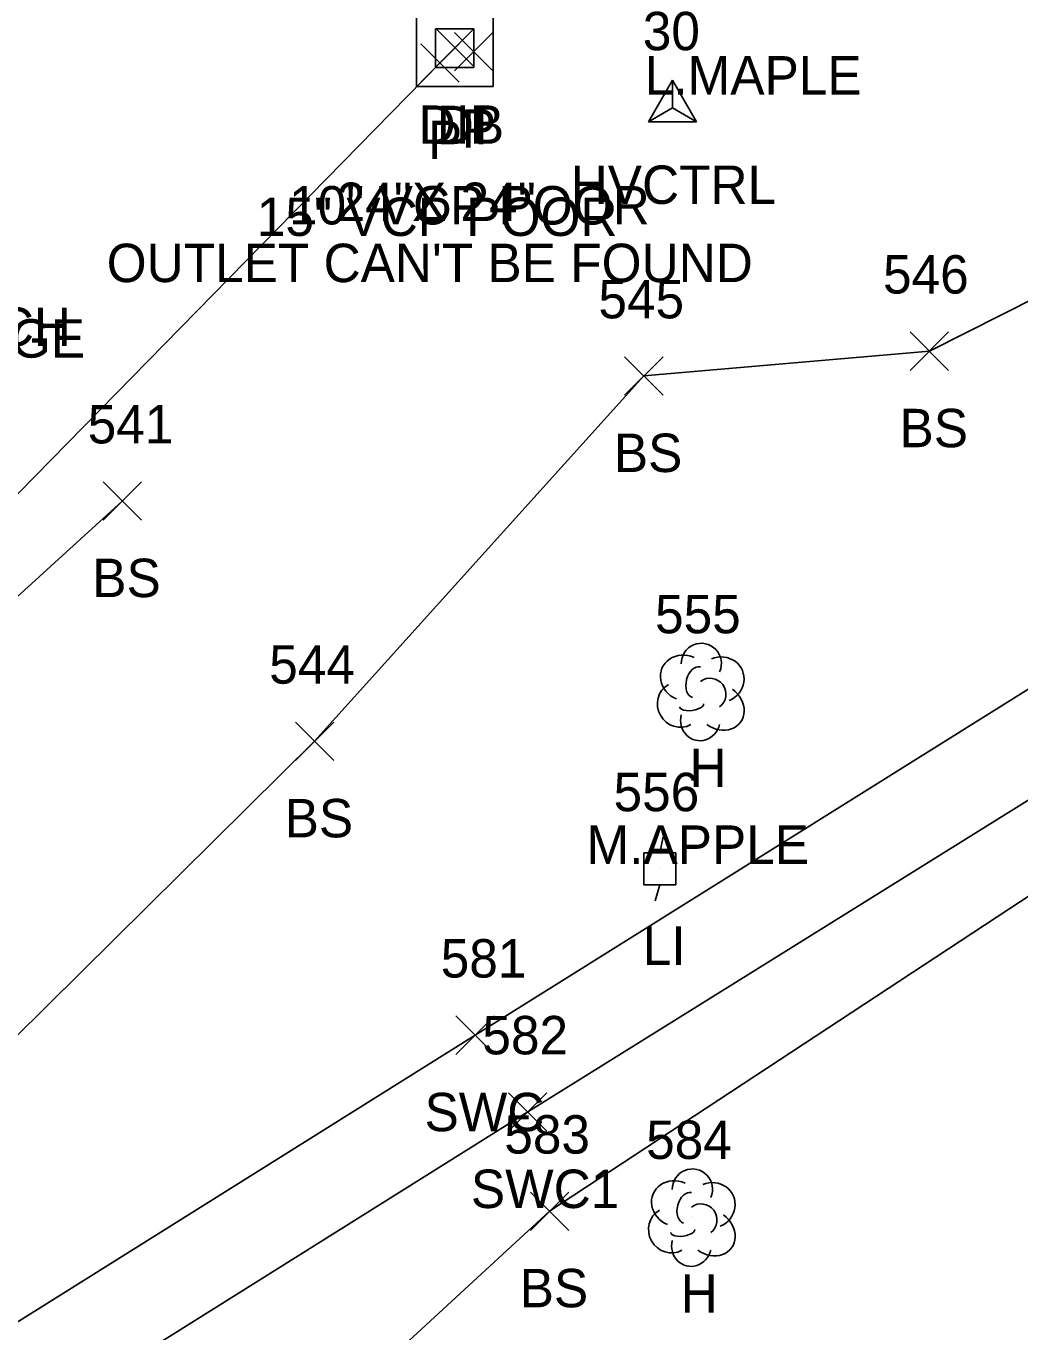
# Model space of a CAD drawing. Extents: x 1462668 to 1465147, y 550359 to 557351.
# Drawn here: x 1464825.9 to 1464877.7, y 552486.8 to 552554.8 of the extents above; entities that cross this region are included whole.
import ezdxf

# ---------------------------------------------------------------- set-up
doc = ezdxf.new("R2010")
doc.units = 0
for name, color, linetype in [('C_A', 7, 'Continuous'), ('C_I', 7, 'Continuous'), ('CPSM', 7, 'Continuous'), ('D_A', 7, 'Continuous'), ('D_C', 7, 'Continuous'), ('D_TIC', 7, 'Continuous'), ('DCP', 7, 'Continuous'), ('DS', 7, 'Continuous'), ('L_A', 7, 'Continuous'), ('L_C', 7, 'Continuous'), ('L_I', 7, 'Continuous'), ('L_TIC', 7, 'Continuous'), ('LELB', 7, 'Continuous'), ('LTD', 7, 'Continuous'), ('R_A', 7, 'Continuous'), ('R_I', 7, 'Continuous'), ('R_TIC', 7, 'Continuous'), ('RSW', 7, 'Continuous'), ('U_A', 7, 'Continuous'), ('U_I', 7, 'Continuous'), ('ULP', 7, 'Continuous')]:
    doc.layers.add(name, color=color, linetype=linetype)

msp = doc.modelspace()

# ---------------------------------------------------------------- linework, layer by layer
at = {"layer": 'CPSM'}
for p, q in [((1464858.341, 552549.777), (1464859.591, 552551.942)), ((1464860.841, 552549.777), (1464859.591, 552551.942)), ((1464859.591, 552550.499), (1464859.591, 552551.942)), ((1464858.341, 552549.777), (1464859.591, 552550.499)), ((1464859.591, 552550.499), (1464859.591, 552550.499)), ((1464859.591, 552550.499), (1464860.841, 552549.777)), ((1464858.341, 552549.777), (1464860.841, 552549.777))]:
    msp.add_line(p, q, dxfattribs=at)
at = {"layer": 'D_TIC'}
for points in [[(1464847.258, 552552.629), (1464849.258, 552554.629)], [(1464849.258, 552552.629), (1464847.258, 552554.629)], [(1464848.234, 552552.429), (1464850.234, 552554.429)], [(1464850.234, 552552.429), (1464848.234, 552554.429)], [(1464846.475, 552551.831), (1464848.475, 552553.831)], [(1464848.475, 552551.831), (1464846.475, 552553.831)]]:
    msp.add_lwpolyline(points, dxfattribs=at)
at = {"layer": 'DCP'}
msp.add_lwpolyline([(1464802.754, 552507.235), (1464847.475, 552552.831)], dxfattribs=at)
at = {"layer": 'DS'}
for p, q in [((1464846.25, 552551.608), (1464846.25, 552555.608)), ((1464850.25, 552555.608), (1464850.25, 552551.608)), ((1464847.25, 552552.608), (1464847.25, 552554.608)), ((1464847.25, 552554.608), (1464849.25, 552554.608)), ((1464849.25, 552554.608), (1464849.25, 552552.608)), ((1464848.256, 552553.609), (1464848.256, 552553.609)), ((1464848.256, 552553.609), (1464848.256, 552553.609)), ((1464849.25, 552552.608), (1464847.25, 552552.608)), ((1464850.25, 552551.608), (1464846.25, 552551.608))]:
    msp.add_line(p, q, dxfattribs=at)
at = {"layer": 'L_TIC'}
for points in [[(1464871.967, 552536.834), (1464873.967, 552538.834)], [(1464873.967, 552536.834), (1464871.967, 552538.834)], [(1464857.093, 552535.543), (1464859.093, 552537.543)], [(1464859.093, 552535.543), (1464857.093, 552537.543)], [(1464829.931, 552529.033), (1464831.931, 552531.033)], [(1464831.931, 552529.033), (1464829.931, 552531.033)], [(1464839.949, 552516.528), (1464841.949, 552518.528)], [(1464841.949, 552516.528), (1464839.949, 552518.528)], [(1464852.19, 552492.066), (1464854.19, 552494.066)], [(1464854.19, 552492.066), (1464852.19, 552494.066)]]:
    msp.add_lwpolyline(points, dxfattribs=at)
at = {"layer": 'LELB'}
for points in [[(1464810.075, 552502.92), (1464823.538, 552500.32), (1464840.949, 552517.528), (1464858.093, 552536.543), (1464872.967, 552537.834), (1464893.717, 552548.289), (1464880.456, 552556.962)], [(1464919.986, 552534.971), (1464889.066, 552516.645), (1464853.19, 552493.066), (1464838.981, 552479.982), (1464840.004, 552467.302), (1464870.453, 552466.87), (1464907.467, 552464.715)], [(1464801.392, 552502.712), (1464812.723, 552513.459), (1464830.931, 552530.033)]]:
    msp.add_lwpolyline(points, dxfattribs=at)
at = {"layer": 'LTD'}
for p, q in [((1464861.041, 552520.149), (1464861.041, 552520.149)), ((1464861.041, 552520.149), (1464861.041, 552520.149)), ((1464860.577, 552492.787), (1464860.577, 552492.787)), ((1464860.577, 552492.787), (1464860.577, 552492.787))]:
    msp.add_line(p, q, dxfattribs=at)
for centre in [(1464861.088, 552521.583), (1464860.624, 552494.221)]:
    msp.add_arc(centre, 1.047, 335.52715, 180.95627, dxfattribs=at)
for centre, major_axis, ratio, start_param, end_param in [((1464860.249, 552520.815), (1.21, -0.512), 0.895232, 1.570796, 4.712389), ((1464862.083, 552520.732), (-1.141, -0.483), 0.949671, 1.570796, 4.712389), ((1464860.833, 552520.607), (-0.208, -0.792), 0.645439, 3.141593, 6.283185), ((1464861.541, 552519.982), (-0.5, 0.667), 0.989748, 3.141593, 6.283185), ((1464859.958, 552519.44), (0.584, -1.042), 0.959034, 3.141593, 6.283185), ((1464862.041, 552519.316), (-1.09, 0.792), 0.841452, 1.570796, 4.712389), ((1464860.583, 552519.399), (-0.625, -0.083), 0.423636, 0, 3.141593), ((1464861.041, 552518.649), (0.265, 1.061), 0.942809, 1.570796, 4.712389), ((1464859.786, 552493.453), (1.21, -0.512), 0.895232, 1.570796, 4.712389), ((1464860.369, 552493.245), (-0.208, -0.792), 0.645439, 3.141593, 6.283185), ((1464861.619, 552493.37), (-1.141, -0.483), 0.949671, 1.570796, 4.712389), ((1464861.077, 552492.62), (-0.5, 0.667), 0.989748, 3.141593, 6.283185), ((1464859.494, 552492.078), (0.584, -1.042), 0.959034, 3.141593, 6.283185), ((1464861.577, 552491.954), (-1.09, 0.792), 0.841452, 1.570796, 4.712389), ((1464860.119, 552492.037), (-0.625, -0.083), 0.423636, 0, 3.141593), ((1464860.578, 552491.287), (0.265, 1.061), 0.942809, 1.570796, 4.712389)]:
    msp.add_ellipse(centre, major_axis=major_axis, ratio=ratio, start_param=start_param, end_param=end_param, dxfattribs=at)
at = {"layer": 'R_TIC'}
for points in [[(1464848.312, 552501.23), (1464850.312, 552503.23)], [(1464850.312, 552501.23), (1464848.312, 552503.23)], [(1464851.049, 552497.233), (1464853.049, 552499.233)], [(1464853.049, 552497.233), (1464851.049, 552499.233)]]:
    msp.add_lwpolyline(points, dxfattribs=at)
at = {"layer": 'RSW'}
for points in [[(1464915.201, 552543.476), (1464884.635, 552524.317), (1464849.312, 552502.23), (1464811.217, 552478.381), (1464802.402, 552472.947), (1464795.812, 552468.295), (1464792.637, 552465.36), (1464790.261, 552462.306), (1464792.645, 552456.479), (1464805.544, 552455.548), (1464830.453, 552453.838), (1464871.786, 552450.71), (1464920.525, 552447.504), (1464964.703, 552444.249), (1464969.112, 552445.273)], [(1464917.507, 552538.983), (1464887.388, 552520.242), (1464852.049, 552498.233), (1464813.823, 552474.305), (1464805.413, 552469.026), (1464798.984, 552464.868), (1464795.363, 552461.268), (1464805.707, 552460.324), (1464871.72, 552455.492), (1464920.401, 552452.145), (1464965.289, 552448.833), (1464968.154, 552449.785)]]:
    msp.add_lwpolyline(points, dxfattribs=at)
at = {"layer": 'ULP'}
for p, q in [((1464859.102, 552512.556), (1464858.936, 552511.723)), ((1464858.102, 552510.056), (1464858.102, 552511.723)), ((1464858.102, 552511.723), (1464859.769, 552511.723)), ((1464859.769, 552511.723), (1464859.769, 552510.056)), ((1464858.936, 552510.889), (1464858.936, 552510.889)), ((1464859.769, 552510.056), (1464858.102, 552510.056)), ((1464858.686, 552509.223), (1464858.936, 552510.056))]:
    msp.add_line(p, q, dxfattribs=at)

# ---------------------------------------------------------------- texts
at = {"layer": 'C_A'}
msp.add_text('HVCTRL', height=2, dxfattribs=at).set_placement((1464854.284, 552545.499))
at = {"layer": 'C_I'}
msp.add_text('30', height=2, dxfattribs=at).set_placement((1464858.04, 552553.499))
at = {"layer": 'D_A'}
for s, p in [('DIB', (1464846.36, 552548.629)), ('DI', (1464847.311, 552548.609)), ('P', (1464846.853, 552547.831)), ('P', (1464848.612, 552548.429))]:
    msp.add_text(s, height=2, dxfattribs=at).set_placement(p)
at = {"layer": 'D_C'}
for s, p in [('10" VCP POOR', (1464839.619, 552544.429)), ('24"X 24"', (1464842.098, 552544.609)), ('15" VCP POOR', (1464837.939, 552543.831)), ("OUTLET CAN'T BE FOUND", (1464830.123, 552541.429))]:
    msp.add_text(s, height=2, dxfattribs=at).set_placement(p)
at = {"layer": 'L_A'}
for s, p in [('CHURCH', (1464816.676, 552538.106)), ('HEDGE', (1464819.485, 552537.498)), ('BS', (1464871.408, 552532.834)), ('BS', (1464856.533, 552531.543)), ('BS', (1464829.372, 552525.033)), ('H', (1464860.474, 552515.149)), ('BS', (1464839.39, 552512.528)), ('BS', (1464851.631, 552488.066)), ('H', (1464860.01, 552487.787))]:
    msp.add_text(s, height=2, dxfattribs=at).set_placement(p)
at = {"layer": 'L_C'}
for s, p in [('L.MAPLE', (1464858.139, 552551.194)), ('M.APPLE', (1464855.104, 552511.149))]:
    msp.add_text(s, height=2, dxfattribs=at).set_placement(p)
at = {"layer": 'L_I'}
for s, p in [('546', (1464870.55, 552540.834)), ('545', (1464855.73, 552539.543)), ('541', (1464829.135, 552533.033)), ('555', (1464858.679, 552523.149)), ('544', (1464838.587, 552520.528)), ('583', (1464850.828, 552496.066)), ('584', (1464858.215, 552495.787))]:
    msp.add_text(s, height=2, dxfattribs=at).set_placement(p)
at = {"layer": 'R_A'}
for s, p in [('SWC', (1464846.674, 552497.23)), ('SWC1', (1464849.088, 552493.233))]:
    msp.add_text(s, height=2, dxfattribs=at).set_placement(p)
at = {"layer": 'R_I'}
for s, p in [('581', (1464847.517, 552505.23)), ('582', (1464849.686, 552501.233))]:
    msp.add_text(s, height=2, dxfattribs=at).set_placement(p)
at = {"layer": 'U_A'}
msp.add_text('LI', height=2, dxfattribs=at).set_placement((1464858.038, 552505.889))
at = {"layer": 'U_I'}
msp.add_text('556', height=2, dxfattribs=at).set_placement((1464856.518, 552513.889))

doc.saveas('drawing.dxf')
